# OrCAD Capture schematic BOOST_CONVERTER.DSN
size A
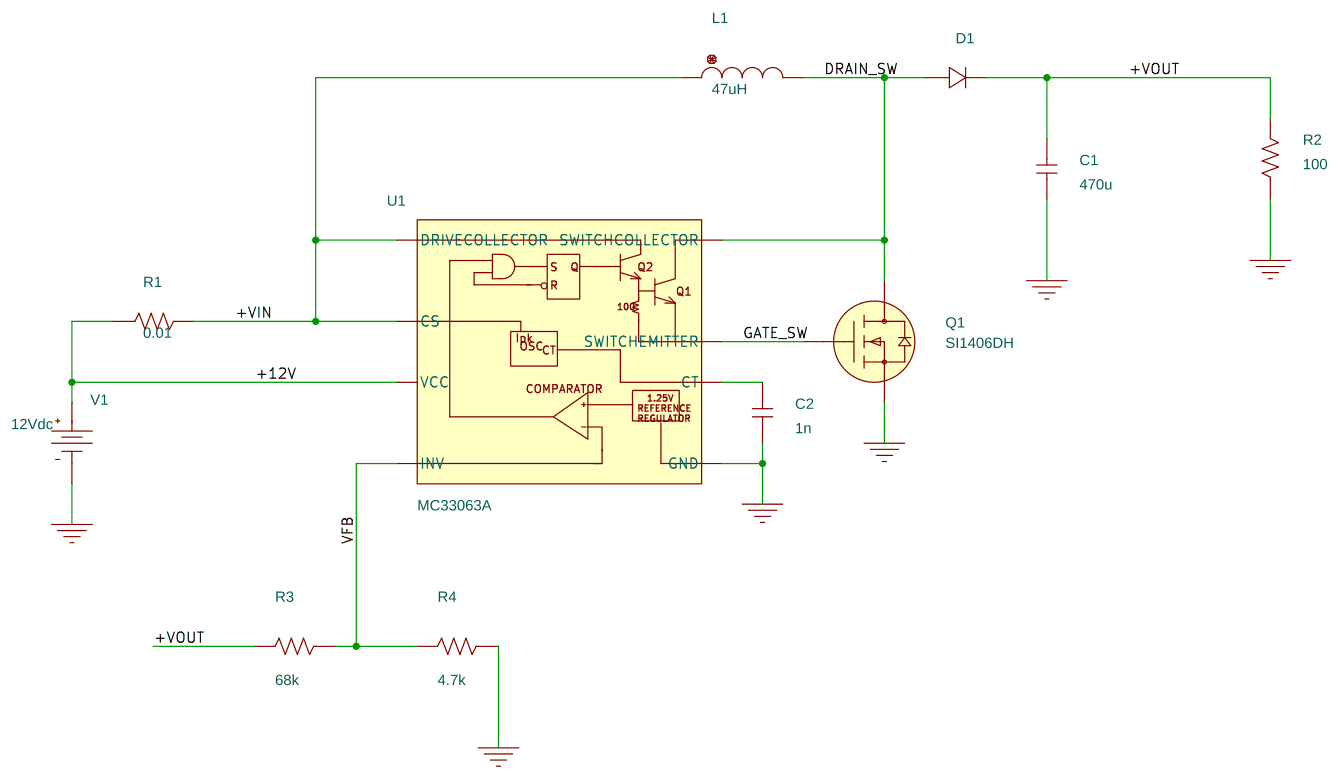
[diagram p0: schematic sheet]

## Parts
C1  470u  [cap196]
C2  1n  [cap196]
D1  Dbreak
L1  47uH  [DISC350x175LS200x100034]
Q1  SI1406DH  [SOT65P210X110-6AN]
R1  0.01  [AXRC05]
R2  100  [AXRC05]
R3  68k  [AXRC05]
R4  4.7k  [AXRC05]
U1  MC33063A  [so8_1_27x4_90]
V1  VDC

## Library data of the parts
C1 C2 = C
D1 = Dbreak
L1 = L
Q1 = Si1406DH
R1-R4 = R
U1 = MC33063A
V1 = VDC: DC: 12Vdc

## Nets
+12V: R1.1 U1.6(VCC) V1.0(+)
+VIN: L1.1 R1.2 U1.7(CS) U1.8(DRIVECOLLECTOR)
0: C1.1 C2.1 Q1.4(S) R2.1 R4.1 U1.4(GND) V1.1(-)
+VOUT: C1.2 D1.1(2) R2.2 R3.2
DRAIN_SW: D1.0(1) L1.2 Q1.2(D) U1.1(SWITCHCOLLECTOR)
GATE_SW: Q1.3(G) U1.2(SWITCHEMITTER)
VFB: R3.1 R4.2 U1.5(INV)
N00677: C2.2 U1.3(CT)
